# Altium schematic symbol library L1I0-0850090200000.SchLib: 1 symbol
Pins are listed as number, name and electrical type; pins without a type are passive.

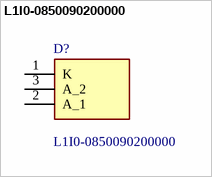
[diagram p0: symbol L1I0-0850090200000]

## L1I0-0850090200000
designator D?
Infrared Emitters - High Power Infrared, 850nm LUXEON IR; Manufacturer_Name: Lumileds; Geometry.Height: 2.87mm
footprint L1I00850090200000
pins: 1 K, 2 A_1, 3 A_2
